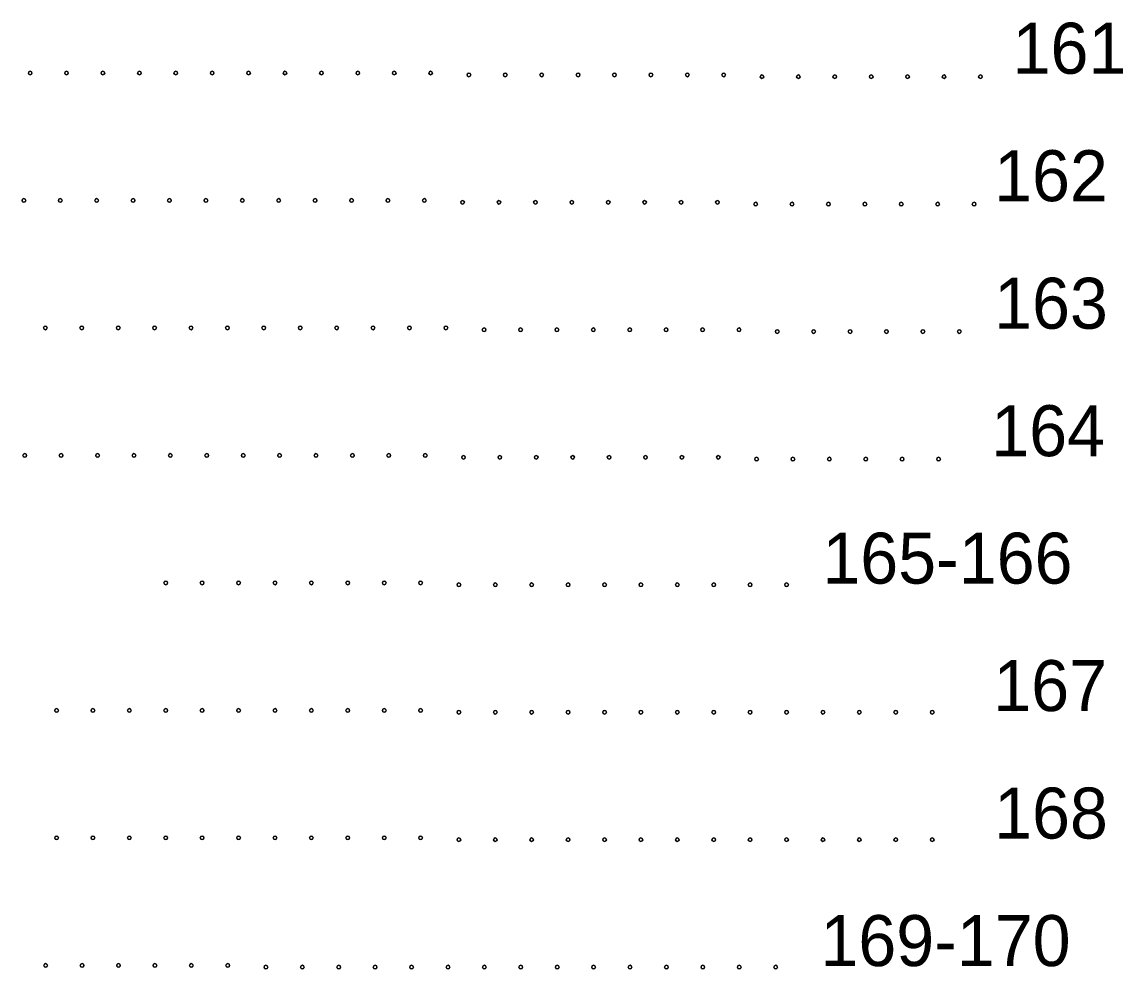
# Model space of a CAD drawing. Extents: x 0 to 1.42, y 0 to 0.92.
# Drawn here: x 0.7964 to 0.9224, y 0.4651 to 0.5735 of the extents above; entities that cross this region are included whole.
import ezdxf

# ---------------------------------------------------------------- set-up
doc = ezdxf.new("R2010")
doc.units = 0
doc.layers.add('DRAFT_Text-Notes', color=7, linetype='Continuous')

msp = doc.modelspace()

# ---------------------------------------------------------------- linework, layer by layer
at = {"layer": 'DRAFT_Text-Notes'}
for centre in [(0.79738, 0.56765), (0.79738, 0.56765), (0.80154, 0.56765), (0.80154, 0.56765), (0.80571, 0.56765), (0.80988, 0.56765), (0.81404, 0.56765), (0.81821, 0.56765), (0.82238, 0.56765), (0.82654, 0.56765), (0.83071, 0.56765), (0.83488, 0.56765), (0.83904, 0.56765), (0.84321, 0.56765), (0.84759, 0.56744), (0.85175, 0.56744), (0.85592, 0.56744), (0.86009, 0.56744), (0.86425, 0.56744), (0.86842, 0.56744), (0.87259, 0.56744), (0.87675, 0.56744), (0.88113, 0.56723), (0.88529, 0.56723), (0.88946, 0.56723), (0.89363, 0.56723), (0.89779, 0.56723), (0.90196, 0.56723), (0.90613, 0.56723), (0.79666, 0.55306), (0.79666, 0.55306), (0.80082, 0.55306), (0.80082, 0.55306), (0.80499, 0.55306), (0.80916, 0.55306), (0.81332, 0.55306), (0.81749, 0.55306), (0.82166, 0.55306), (0.82582, 0.55306), (0.82999, 0.55306), (0.83416, 0.55306), (0.83832, 0.55306), (0.84249, 0.55306), (0.84687, 0.55285), (0.85103, 0.55285), (0.8552, 0.55285), (0.85937, 0.55285), (0.86353, 0.55285), (0.8677, 0.55285), (0.87187, 0.55285), (0.87603, 0.55285), (0.88041, 0.55264), (0.88457, 0.55264), (0.88874, 0.55264), (0.89291, 0.55264), (0.89707, 0.55264), (0.90124, 0.55264), (0.90541, 0.55264), (0.79912, 0.53847), (0.79912, 0.53847), (0.80329, 0.53847), (0.80329, 0.53847), (0.80746, 0.53847), (0.81162, 0.53847), (0.81579, 0.53847), (0.81996, 0.53847), (0.82412, 0.53847), (0.82829, 0.53847), (0.83246, 0.53847), (0.83662, 0.53847), (0.84079, 0.53847), (0.84496, 0.53847), (0.84933, 0.53826), (0.8535, 0.53826), (0.85766, 0.53826), (0.86183, 0.53826), (0.866, 0.53826), (0.87016, 0.53826), (0.87433, 0.53826), (0.8785, 0.53826), (0.88287, 0.53805), (0.88704, 0.53805), (0.89121, 0.53805), (0.89537, 0.53805), (0.89954, 0.53805), (0.90371, 0.53805), (0.79676, 0.52387), (0.79676, 0.52387), (0.80092, 0.52387), (0.80092, 0.52387), (0.80509, 0.52387), (0.80926, 0.52387), (0.81342, 0.52387), (0.81759, 0.52387), (0.82176, 0.52387), (0.82592, 0.52387), (0.83009, 0.52387), (0.83426, 0.52387), (0.83842, 0.52387), (0.84259, 0.52387), (0.84697, 0.52366), (0.85113, 0.52366), (0.8553, 0.52366), (0.85947, 0.52366), (0.86363, 0.52366), (0.8678, 0.52366), (0.87197, 0.52366), (0.87613, 0.52366), (0.88051, 0.52346), (0.88467, 0.52346), (0.88884, 0.52346), (0.89301, 0.52346), (0.89717, 0.52346), (0.90134, 0.52346), (0.8129, 0.50928), (0.81706, 0.50928), (0.82123, 0.50928), (0.8254, 0.50928), (0.82956, 0.50928), (0.83373, 0.50928), (0.8379, 0.50928), (0.84206, 0.50928), (0.84644, 0.50907), (0.85061, 0.50907), (0.85477, 0.50907), (0.85894, 0.50907), (0.86311, 0.50907), (0.86727, 0.50907), (0.87144, 0.50907), (0.87561, 0.50907), (0.87977, 0.50907), (0.88394, 0.50907), (0.8004, 0.49469), (0.8004, 0.49469), (0.80456, 0.49469), (0.80873, 0.49469), (0.8129, 0.49469), (0.81706, 0.49469), (0.82123, 0.49469), (0.8254, 0.49469), (0.82956, 0.49469), (0.83373, 0.49469), (0.8379, 0.49469), (0.84206, 0.49469), (0.84644, 0.49448), (0.85061, 0.49448), (0.85477, 0.49448), (0.85894, 0.49448), (0.86311, 0.49448), (0.86727, 0.49448), (0.87144, 0.49448), (0.87561, 0.49448), (0.87977, 0.49448), (0.88394, 0.49448), (0.88811, 0.49448), (0.89227, 0.49448), (0.89644, 0.49448), (0.90061, 0.49448), (0.8004, 0.4801), (0.8004, 0.4801), (0.80456, 0.4801), (0.80873, 0.4801), (0.8129, 0.4801), (0.81706, 0.4801), (0.82123, 0.4801), (0.8254, 0.4801), (0.82956, 0.4801), (0.83373, 0.4801), (0.8379, 0.4801), (0.84206, 0.4801), (0.84644, 0.47989), (0.85061, 0.47989), (0.85477, 0.47989), (0.85894, 0.47989), (0.86311, 0.47989), (0.86727, 0.47989), (0.87144, 0.47989), (0.87561, 0.47989), (0.87977, 0.47989), (0.88394, 0.47989), (0.88811, 0.47989), (0.89227, 0.47989), (0.89644, 0.47989), (0.90061, 0.47989), (0.79915, 0.4655), (0.80332, 0.4655), (0.80749, 0.4655), (0.81165, 0.4655), (0.81582, 0.4655), (0.81999, 0.4655), (0.82436, 0.4653), (0.82853, 0.4653), (0.8327, 0.4653), (0.83686, 0.4653), (0.84103, 0.4653), (0.8452, 0.4653), (0.84936, 0.4653), (0.85353, 0.4653), (0.8577, 0.4653), (0.86186, 0.4653), (0.86603, 0.4653), (0.8702, 0.4653), (0.87436, 0.4653), (0.87853, 0.4653), (0.8827, 0.4653)]:
    msp.add_circle(centre, 0.000208, dxfattribs=at)
for centre, start, end in [((0.79738, 0.56765), 0, 180), ((0.79738, 0.56765), 0, 180), ((0.79738, 0.56765), 180, 0), ((0.79738, 0.56765), 180, 0), ((0.80154, 0.56765), 0, 180), ((0.80154, 0.56765), 0, 180), ((0.80154, 0.56765), 180, 0), ((0.80154, 0.56765), 180, 0), ((0.80571, 0.56765), 0, 180), ((0.80571, 0.56765), 180, 0), ((0.80988, 0.56765), 0, 180), ((0.80988, 0.56765), 180, 0), ((0.81404, 0.56765), 0, 180), ((0.81404, 0.56765), 180, 0), ((0.81821, 0.56765), 0, 180), ((0.81821, 0.56765), 180, 0), ((0.82238, 0.56765), 0, 180), ((0.82238, 0.56765), 180, 0), ((0.82654, 0.56765), 0, 180), ((0.82654, 0.56765), 180, 0), ((0.83071, 0.56765), 0, 180), ((0.83071, 0.56765), 180, 0), ((0.83488, 0.56765), 0, 180), ((0.83488, 0.56765), 180, 0), ((0.83904, 0.56765), 0, 180), ((0.83904, 0.56765), 180, 0), ((0.84321, 0.56765), 0, 180), ((0.84321, 0.56765), 180, 0), ((0.84759, 0.56744), 0, 180), ((0.84759, 0.56744), 180, 0), ((0.85175, 0.56744), 0, 180), ((0.85175, 0.56744), 180, 0), ((0.85592, 0.56744), 0, 180), ((0.85592, 0.56744), 180, 0), ((0.86009, 0.56744), 0, 180), ((0.86009, 0.56744), 180, 0), ((0.86425, 0.56744), 0, 180), ((0.86425, 0.56744), 180, 0), ((0.86842, 0.56744), 0, 180), ((0.86842, 0.56744), 180, 0), ((0.87259, 0.56744), 0, 180), ((0.87259, 0.56744), 180, 0), ((0.87675, 0.56744), 0, 180), ((0.87675, 0.56744), 180, 0), ((0.88113, 0.56723), 0, 180), ((0.88113, 0.56723), 180, 0), ((0.88529, 0.56723), 0, 180), ((0.88529, 0.56723), 180, 0), ((0.88946, 0.56723), 0, 180), ((0.88946, 0.56723), 180, 0), ((0.89363, 0.56723), 0, 180), ((0.89363, 0.56723), 180, 0), ((0.89779, 0.56723), 0, 180), ((0.89779, 0.56723), 180, 0), ((0.90196, 0.56723), 0, 180), ((0.90196, 0.56723), 180, 0), ((0.90613, 0.56723), 0, 180), ((0.90613, 0.56723), 180, 0), ((0.79666, 0.55306), 0, 180), ((0.79666, 0.55306), 0, 180), ((0.80082, 0.55306), 0, 180), ((0.80082, 0.55306), 0, 180), ((0.80499, 0.55306), 0, 180), ((0.80916, 0.55306), 0, 180), ((0.81332, 0.55306), 0, 180), ((0.81749, 0.55306), 0, 180), ((0.82166, 0.55306), 0, 180), ((0.82582, 0.55306), 0, 180), ((0.82999, 0.55306), 0, 180), ((0.83416, 0.55306), 0, 180), ((0.83832, 0.55306), 0, 180), ((0.84249, 0.55306), 0, 180), ((0.79666, 0.55306), 180, 0), ((0.79666, 0.55306), 180, 0), ((0.80082, 0.55306), 180, 0), ((0.80082, 0.55306), 180, 0), ((0.80499, 0.55306), 180, 0), ((0.80916, 0.55306), 180, 0), ((0.81332, 0.55306), 180, 0), ((0.81749, 0.55306), 180, 0), ((0.82166, 0.55306), 180, 0), ((0.82582, 0.55306), 180, 0), ((0.82999, 0.55306), 180, 0), ((0.83416, 0.55306), 180, 0), ((0.83832, 0.55306), 180, 0), ((0.84249, 0.55306), 180, 0), ((0.84687, 0.55285), 0, 180), ((0.84687, 0.55285), 180, 0), ((0.85103, 0.55285), 0, 180), ((0.85103, 0.55285), 180, 0), ((0.8552, 0.55285), 0, 180), ((0.8552, 0.55285), 180, 0), ((0.85937, 0.55285), 0, 180), ((0.85937, 0.55285), 180, 0), ((0.86353, 0.55285), 0, 180), ((0.86353, 0.55285), 180, 0), ((0.8677, 0.55285), 0, 180), ((0.8677, 0.55285), 180, 0), ((0.87187, 0.55285), 0, 180), ((0.87187, 0.55285), 180, 0), ((0.87603, 0.55285), 0, 180), ((0.87603, 0.55285), 180, 0), ((0.88041, 0.55264), 0, 180), ((0.88041, 0.55264), 180, 0), ((0.88457, 0.55264), 0, 180), ((0.88457, 0.55264), 180, 0), ((0.88874, 0.55264), 0, 180), ((0.88874, 0.55264), 180, 0), ((0.89291, 0.55264), 0, 180), ((0.89291, 0.55264), 180, 0), ((0.89707, 0.55264), 0, 180), ((0.89707, 0.55264), 180, 0), ((0.90124, 0.55264), 0, 180), ((0.90124, 0.55264), 180, 0), ((0.90541, 0.55264), 0, 180), ((0.90541, 0.55264), 180, 0), ((0.79912, 0.53847), 0, 180), ((0.79912, 0.53847), 0, 180), ((0.79912, 0.53847), 180, 0), ((0.79912, 0.53847), 180, 0), ((0.80329, 0.53847), 0, 180), ((0.80329, 0.53847), 0, 180), ((0.80329, 0.53847), 180, 0), ((0.80329, 0.53847), 180, 0), ((0.80746, 0.53847), 0, 180), ((0.80746, 0.53847), 180, 0), ((0.81162, 0.53847), 0, 180), ((0.81162, 0.53847), 180, 0), ((0.81579, 0.53847), 0, 180), ((0.81579, 0.53847), 180, 0), ((0.81996, 0.53847), 0, 180), ((0.81996, 0.53847), 180, 0), ((0.82412, 0.53847), 0, 180), ((0.82412, 0.53847), 180, 0), ((0.82829, 0.53847), 0, 180), ((0.82829, 0.53847), 180, 0), ((0.83246, 0.53847), 0, 180), ((0.83246, 0.53847), 180, 0), ((0.83662, 0.53847), 0, 180), ((0.83662, 0.53847), 180, 0), ((0.84079, 0.53847), 0, 180), ((0.84079, 0.53847), 180, 0), ((0.84496, 0.53847), 0, 180), ((0.84496, 0.53847), 180, 0), ((0.84933, 0.53826), 0, 180), ((0.84933, 0.53826), 180, 0), ((0.8535, 0.53826), 0, 180), ((0.8535, 0.53826), 180, 0), ((0.85766, 0.53826), 0, 180), ((0.85766, 0.53826), 180, 0), ((0.86183, 0.53826), 0, 180), ((0.86183, 0.53826), 180, 0), ((0.866, 0.53826), 0, 180), ((0.866, 0.53826), 180, 0), ((0.87016, 0.53826), 0, 180), ((0.87016, 0.53826), 180, 0), ((0.87433, 0.53826), 0, 180), ((0.87433, 0.53826), 180, 0), ((0.8785, 0.53826), 0, 180), ((0.8785, 0.53826), 180, 0), ((0.88287, 0.53805), 0, 180), ((0.88287, 0.53805), 180, 0), ((0.88704, 0.53805), 0, 180), ((0.88704, 0.53805), 180, 0), ((0.89121, 0.53805), 0, 180), ((0.89121, 0.53805), 180, 0), ((0.89537, 0.53805), 0, 180), ((0.89537, 0.53805), 180, 0), ((0.89954, 0.53805), 0, 180), ((0.89954, 0.53805), 180, 0), ((0.90371, 0.53805), 0, 180), ((0.90371, 0.53805), 180, 0), ((0.79676, 0.52387), 0, 180), ((0.79676, 0.52387), 0, 180), ((0.79676, 0.52387), 180, 0), ((0.79676, 0.52387), 180, 0), ((0.80092, 0.52387), 0, 180), ((0.80092, 0.52387), 0, 180), ((0.80092, 0.52387), 180, 0), ((0.80092, 0.52387), 180, 0), ((0.80509, 0.52387), 0, 180), ((0.80509, 0.52387), 180, 0), ((0.80926, 0.52387), 0, 180), ((0.80926, 0.52387), 180, 0), ((0.81342, 0.52387), 0, 180), ((0.81342, 0.52387), 180, 0), ((0.81759, 0.52387), 0, 180), ((0.81759, 0.52387), 180, 0), ((0.82176, 0.52387), 0, 180), ((0.82176, 0.52387), 180, 0), ((0.82592, 0.52387), 0, 180), ((0.82592, 0.52387), 180, 0), ((0.83009, 0.52387), 0, 180), ((0.83009, 0.52387), 180, 0), ((0.83426, 0.52387), 0, 180), ((0.83426, 0.52387), 180, 0), ((0.83842, 0.52387), 0, 180), ((0.83842, 0.52387), 180, 0), ((0.84259, 0.52387), 0, 180), ((0.84259, 0.52387), 180, 0), ((0.84697, 0.52366), 0, 180), ((0.84697, 0.52366), 180, 0), ((0.85113, 0.52366), 0, 180), ((0.85113, 0.52366), 180, 0), ((0.8553, 0.52366), 0, 180), ((0.8553, 0.52366), 180, 0), ((0.85947, 0.52366), 0, 180), ((0.85947, 0.52366), 180, 0), ((0.86363, 0.52366), 0, 180), ((0.86363, 0.52366), 180, 0), ((0.8678, 0.52366), 0, 180), ((0.8678, 0.52366), 180, 0), ((0.87197, 0.52366), 0, 180), ((0.87197, 0.52366), 180, 0), ((0.87613, 0.52366), 0, 180), ((0.87613, 0.52366), 180, 0), ((0.88051, 0.52346), 0, 180), ((0.88051, 0.52346), 180, 0), ((0.88467, 0.52346), 0, 180), ((0.88467, 0.52346), 180, 0), ((0.88884, 0.52346), 0, 180), ((0.88884, 0.52346), 180, 0), ((0.89301, 0.52346), 0, 180), ((0.89301, 0.52346), 180, 0), ((0.89717, 0.52346), 0, 180), ((0.89717, 0.52346), 180, 0), ((0.90134, 0.52346), 0, 180), ((0.90134, 0.52346), 180, 0), ((0.8129, 0.50928), 0, 180), ((0.8129, 0.50928), 180, 0), ((0.81706, 0.50928), 0, 180), ((0.81706, 0.50928), 180, 0), ((0.82123, 0.50928), 0, 180), ((0.82123, 0.50928), 180, 0), ((0.8254, 0.50928), 0, 180), ((0.8254, 0.50928), 180, 0), ((0.82956, 0.50928), 0, 180), ((0.82956, 0.50928), 180, 0), ((0.83373, 0.50928), 0, 180), ((0.83373, 0.50928), 180, 0), ((0.8379, 0.50928), 0, 180), ((0.8379, 0.50928), 180, 0), ((0.84206, 0.50928), 0, 180), ((0.84206, 0.50928), 180, 0), ((0.84644, 0.50907), 0, 180), ((0.84644, 0.50907), 180, 0), ((0.85061, 0.50907), 0, 180), ((0.85061, 0.50907), 180, 0), ((0.85477, 0.50907), 0, 180), ((0.85477, 0.50907), 180, 0), ((0.85894, 0.50907), 0, 180), ((0.85894, 0.50907), 180, 0), ((0.86311, 0.50907), 0, 180), ((0.86311, 0.50907), 180, 0), ((0.86727, 0.50907), 0, 180), ((0.86727, 0.50907), 180, 0), ((0.87144, 0.50907), 0, 180), ((0.87144, 0.50907), 180, 0), ((0.87561, 0.50907), 0, 180), ((0.87561, 0.50907), 180, 0), ((0.87977, 0.50907), 0, 180), ((0.87977, 0.50907), 180, 0), ((0.88394, 0.50907), 0, 180), ((0.88394, 0.50907), 180, 0), ((0.8004, 0.49469), 0, 180), ((0.8004, 0.49469), 0, 180), ((0.8004, 0.49469), 180, 0), ((0.8004, 0.49469), 180, 0), ((0.80456, 0.49469), 0, 180), ((0.80456, 0.49469), 180, 0), ((0.80873, 0.49469), 0, 180), ((0.80873, 0.49469), 180, 0), ((0.8129, 0.49469), 0, 180), ((0.8129, 0.49469), 180, 0), ((0.81706, 0.49469), 0, 180), ((0.81706, 0.49469), 180, 0), ((0.82123, 0.49469), 0, 180), ((0.82123, 0.49469), 180, 0), ((0.8254, 0.49469), 0, 180), ((0.8254, 0.49469), 180, 0), ((0.82956, 0.49469), 0, 180), ((0.82956, 0.49469), 180, 0), ((0.83373, 0.49469), 0, 180), ((0.83373, 0.49469), 180, 0), ((0.8379, 0.49469), 0, 180), ((0.8379, 0.49469), 180, 0), ((0.84206, 0.49469), 0, 180), ((0.84206, 0.49469), 180, 0), ((0.84644, 0.49448), 0, 180), ((0.84644, 0.49448), 180, 0), ((0.85061, 0.49448), 0, 180), ((0.85061, 0.49448), 180, 0), ((0.85477, 0.49448), 0, 180), ((0.85477, 0.49448), 180, 0), ((0.85894, 0.49448), 0, 180), ((0.85894, 0.49448), 180, 0), ((0.86311, 0.49448), 0, 180), ((0.86311, 0.49448), 180, 0), ((0.86727, 0.49448), 0, 180), ((0.86727, 0.49448), 180, 0), ((0.87144, 0.49448), 0, 180), ((0.87144, 0.49448), 180, 0), ((0.87561, 0.49448), 0, 180), ((0.87561, 0.49448), 180, 0), ((0.87977, 0.49448), 0, 180), ((0.87977, 0.49448), 180, 0), ((0.88394, 0.49448), 0, 180), ((0.88394, 0.49448), 180, 0), ((0.88811, 0.49448), 0, 180), ((0.88811, 0.49448), 180, 0), ((0.89227, 0.49448), 0, 180), ((0.89227, 0.49448), 180, 0), ((0.89644, 0.49448), 0, 180), ((0.89644, 0.49448), 180, 0), ((0.90061, 0.49448), 0, 180), ((0.90061, 0.49448), 180, 0), ((0.8004, 0.4801), 0, 180), ((0.8004, 0.4801), 0, 180), ((0.8004, 0.4801), 180, 0), ((0.8004, 0.4801), 180, 0), ((0.80456, 0.4801), 0, 180), ((0.80456, 0.4801), 180, 0), ((0.80873, 0.4801), 0, 180), ((0.80873, 0.4801), 180, 0), ((0.8129, 0.4801), 0, 180), ((0.8129, 0.4801), 180, 0), ((0.81706, 0.4801), 0, 180), ((0.81706, 0.4801), 180, 0), ((0.82123, 0.4801), 0, 180), ((0.82123, 0.4801), 180, 0), ((0.8254, 0.4801), 0, 180), ((0.8254, 0.4801), 180, 0), ((0.82956, 0.4801), 0, 180), ((0.82956, 0.4801), 180, 0), ((0.83373, 0.4801), 0, 180), ((0.83373, 0.4801), 180, 0), ((0.8379, 0.4801), 0, 180), ((0.8379, 0.4801), 180, 0), ((0.84206, 0.4801), 0, 180), ((0.84206, 0.4801), 180, 0), ((0.84644, 0.47989), 0, 180), ((0.85061, 0.47989), 0, 180), ((0.85477, 0.47989), 0, 180), ((0.85894, 0.47989), 0, 180), ((0.86311, 0.47989), 0, 180), ((0.86727, 0.47989), 0, 180), ((0.87144, 0.47989), 0, 180), ((0.87561, 0.47989), 0, 180), ((0.87977, 0.47989), 0, 180), ((0.88394, 0.47989), 0, 180), ((0.88811, 0.47989), 0, 180), ((0.89227, 0.47989), 0, 180), ((0.89644, 0.47989), 0, 180), ((0.90061, 0.47989), 0, 180), ((0.84644, 0.47989), 180, 0), ((0.85061, 0.47989), 180, 0), ((0.85477, 0.47989), 180, 0), ((0.85894, 0.47989), 180, 0), ((0.86311, 0.47989), 180, 0), ((0.86727, 0.47989), 180, 0), ((0.87144, 0.47989), 180, 0), ((0.87561, 0.47989), 180, 0), ((0.87977, 0.47989), 180, 0), ((0.88394, 0.47989), 180, 0), ((0.88811, 0.47989), 180, 0), ((0.89227, 0.47989), 180, 0), ((0.89644, 0.47989), 180, 0), ((0.90061, 0.47989), 180, 0), ((0.79915, 0.4655), 0, 180), ((0.79915, 0.4655), 180, 0), ((0.80332, 0.4655), 0, 180), ((0.80332, 0.4655), 180, 0), ((0.80749, 0.4655), 0, 180), ((0.80749, 0.4655), 180, 0), ((0.81165, 0.4655), 0, 180), ((0.81165, 0.4655), 180, 0), ((0.81582, 0.4655), 0, 180), ((0.81582, 0.4655), 180, 0), ((0.81999, 0.4655), 0, 180), ((0.81999, 0.4655), 180, 0), ((0.82436, 0.4653), 0, 180), ((0.82436, 0.4653), 180, 0), ((0.82853, 0.4653), 0, 180), ((0.82853, 0.4653), 180, 0), ((0.8327, 0.4653), 0, 180), ((0.8327, 0.4653), 180, 0), ((0.83686, 0.4653), 0, 180), ((0.83686, 0.4653), 180, 0), ((0.84103, 0.4653), 0, 180), ((0.84103, 0.4653), 180, 0), ((0.8452, 0.4653), 0, 180), ((0.8452, 0.4653), 180, 0), ((0.84936, 0.4653), 0, 180), ((0.84936, 0.4653), 180, 0), ((0.85353, 0.4653), 0, 180), ((0.85353, 0.4653), 180, 0), ((0.8577, 0.4653), 0, 180), ((0.8577, 0.4653), 180, 0), ((0.86186, 0.4653), 0, 180), ((0.86186, 0.4653), 180, 0), ((0.86603, 0.4653), 0, 180), ((0.86603, 0.4653), 180, 0), ((0.8702, 0.4653), 0, 180), ((0.8702, 0.4653), 180, 0), ((0.87436, 0.4653), 0, 180), ((0.87436, 0.4653), 180, 0), ((0.87853, 0.4653), 0, 180), ((0.87853, 0.4653), 180, 0), ((0.8827, 0.4653), 0, 180), ((0.8827, 0.4653), 180, 0)]:
    msp.add_arc(centre, 0.000208, start, end, dxfattribs=at)

# ---------------------------------------------------------------- texts
for s, p in [('161', (0.90981, 0.56757)), ('162', (0.9077, 0.55298)), ('163', (0.9077, 0.53838)), ('164', (0.90737, 0.52379)), ('165-166', (0.88804, 0.5092)), ('167', (0.9076, 0.49461)), ('168', (0.9077, 0.48002)), ('169-170', (0.88782, 0.46542))]:
    msp.add_text(s, height=0.005833, dxfattribs=at).set_placement(p)

doc.saveas('drawing.dxf')
